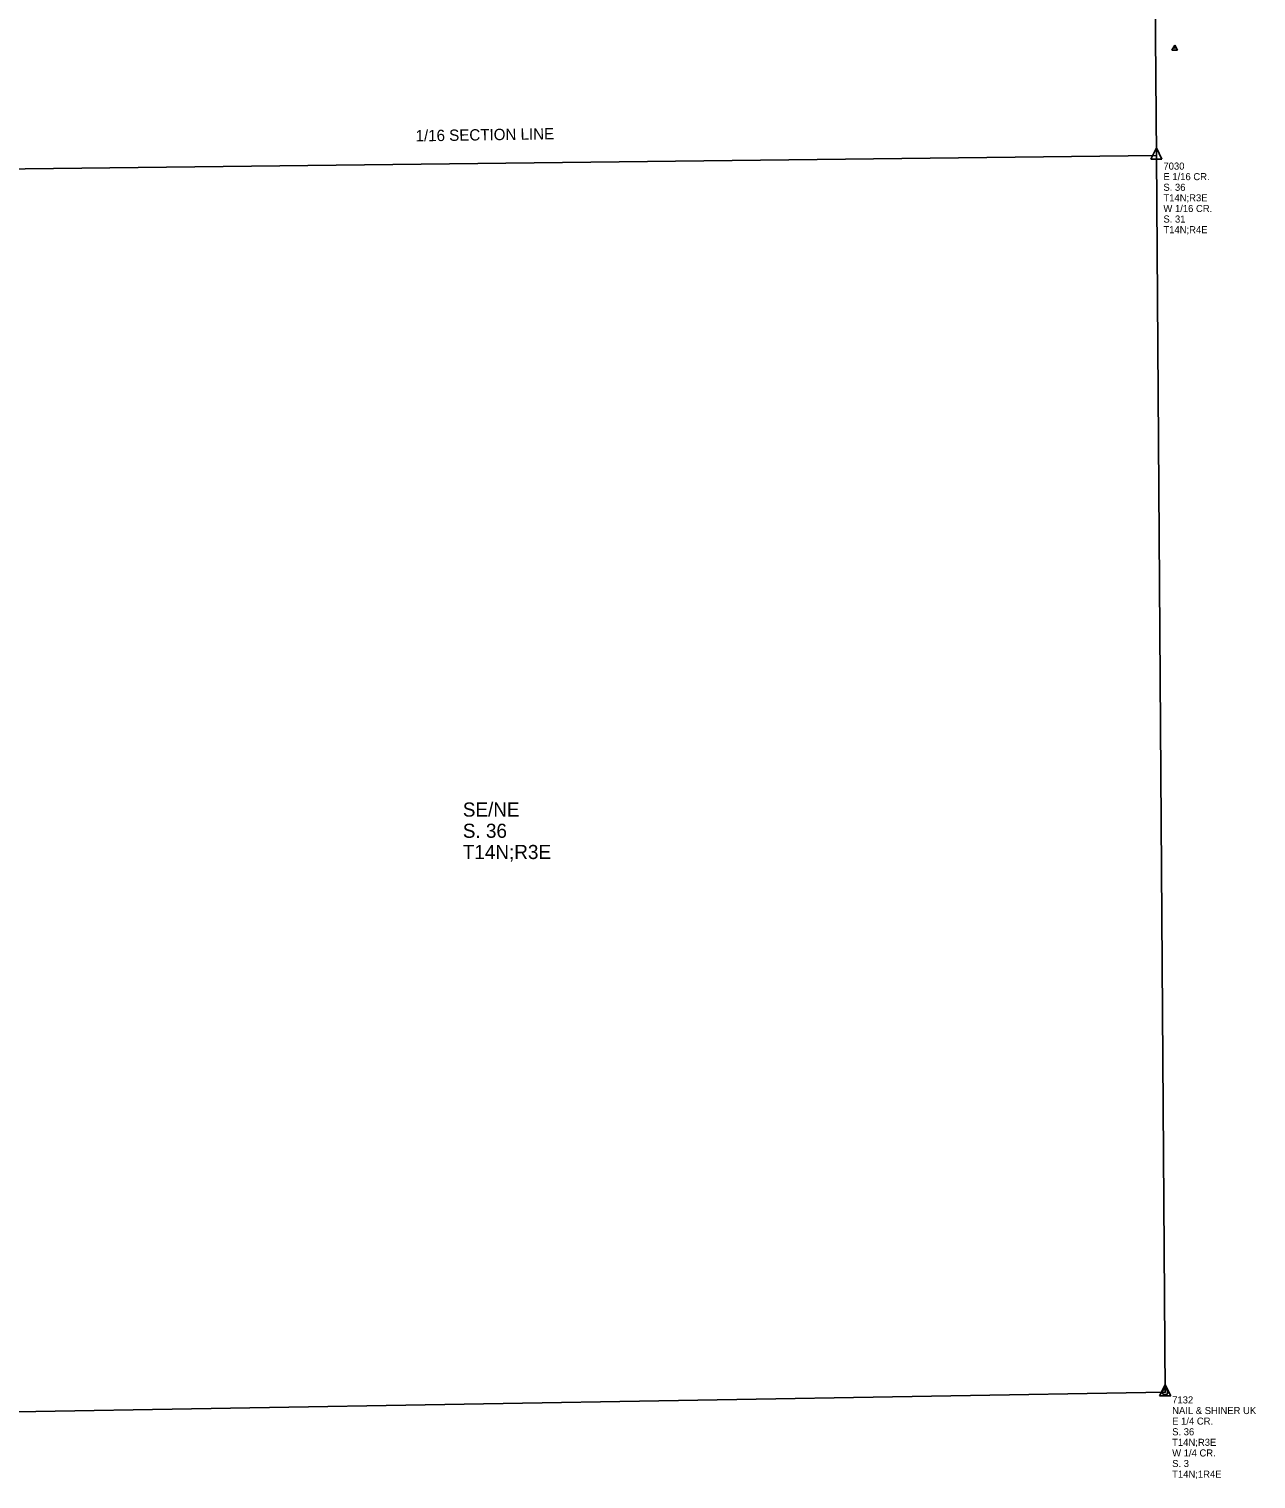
# Model space of a CAD drawing. Extents: x 1688544 to 1704497, y 535668 to 545444.
# Drawn here: x 1692576 to 1693878, y 536190 to 537729 of the extents above; entities that cross this region are included whole.
import ezdxf

# ---------------------------------------------------------------- set-up
doc = ezdxf.new("R2010")
doc.units = 0
for name, color, linetype in [('Default', 7, 'Continuous'), ('S_CAL_CORNER', 7, 'Continuous'), ('S_CAL_CORNER_ANNOT', 7, 'Continuous'), ('S_IRON_PIN', 7, 'Continuous'), ('S_IRON_PIN_ANNOT', 7, 'Continuous'), ('S_QSECTION', 7, 'Continuous'), ('S_SECONDARY_CTL', 7, 'Continuous'), ('S_SECTION', 7, 'Continuous'), ('S_SECTION_ANNOT', 7, 'Continuous'), ('S_SIXTEEN_SECTION', 7, 'Continuous')]:
    doc.layers.add(name, color=color, linetype=linetype)

msp = doc.modelspace()

# ---------------------------------------------------------------- linework, layer by layer
at = {"layer": 'S_CAL_CORNER'}
for p, q in [((1693772.7, 537602.7), (1693766.8, 537590.9)), ((1693772.7, 537602.7), (1693766.8, 537590.9)), ((1693772.7, 537602.7), (1693766.8, 537590.9)), ((1693766.8, 537590.9), (1693778.5, 537590.9)), ((1693766.8, 537590.9), (1693778.5, 537590.9)), ((1693766.8, 537590.9), (1693778.5, 537590.9)), ((1693772.7, 537602.7), (1693778.5, 537590.9)), ((1693772.7, 537602.7), (1693778.5, 537590.9)), ((1693772.7, 537602.7), (1693778.5, 537590.9)), ((1693781.9, 536290.3), (1693776.1, 536278.5)), ((1693781.9, 536290.3), (1693787.8, 536278.5)), ((1693776.1, 536278.5), (1693787.8, 536278.5))]:
    msp.add_line(p, q, dxfattribs=at)
at = {"layer": 'S_IRON_PIN'}
for radius in [2.91, 0.411, 0.212, 0.262, 0.145, 0.0581, 0.0822]:
    msp.add_circle((1693781.9, 536282.4), radius, dxfattribs=at)
at = {"layer": 'S_QSECTION'}
msp.add_line((1692471.9, 536259.9), (1693781.9, 536282.4), dxfattribs=at)
at = {"layer": 'S_SECONDARY_CTL'}
for p, q in [((1693792.1, 537711.6), (1693789.1, 537706.6)), ((1693789.1, 537706.6), (1693795.1, 537706.6)), ((1693792.1, 537711.6), (1693795.1, 537706.6))]:
    msp.add_line(p, q, dxfattribs=at)
for radius in [0.311, 0.183, 0.103]:
    msp.add_circle((1693792.1, 537709), radius, dxfattribs=at)
at = {"layer": 'S_SECTION'}
for p, q in [((1693763.3, 538907.1), (1693772.6, 537594.7)), ((1693772.6, 537594.7), (1693781.9, 536282.4))]:
    msp.add_line(p, q, dxfattribs=at)
at = {"layer": 'S_SIXTEEN_SECTION'}
msp.add_line((1692463.3, 537579.4), (1693772.6, 537594.7), dxfattribs=at)

# ---------------------------------------------------------------- texts
at = {"layer": 'Default'}
for s, p in [('SE/NE', (1693036.3, 536893.1)), ('S. 36', (1693036.3, 536870.6)), ('T14N;R3E', (1693036.3, 536848.1))]:
    msp.add_text(s, height=15, dxfattribs=at).set_placement(p)
at = {"layer": 'S_CAL_CORNER_ANNOT'}
for s, p in [('7030', (1693780.1, 537579.7)), ('E 1/16 CR.', (1693780.1, 537568.5)), ('S. 36 ', (1693780.1, 537557.2)), ('T14N;R3E', (1693780.1, 537546)), ('W 1/16 CR.', (1693780.1, 537534.7)), ('S. 31', (1693780.1, 537523.5)), ('T14N;R4E', (1693780.1, 537512.2))]:
    msp.add_text(s, height=7.5, dxfattribs=at).set_placement(p)
at = {"layer": 'S_IRON_PIN_ANNOT'}
for s, p in [('7132', (1693789.4, 536270.4)), ('NAIL & SHINER UK ', (1693789.4, 536259.1)), ('E 1/4 CR. ', (1693789.4, 536247.9)), ('S. 36', (1693789.4, 536236.6)), ('W 1/4 CR.', (1693789.4, 536214.1)), ('T14N;R3E', (1693789.4, 536225.4)), ('S. 3', (1693789.4, 536202.9)), ('T14N;1R4E', (1693789.4, 536191.6))]:
    msp.add_text(s, height=7.5, dxfattribs=at).set_placement(p)
at = {"layer": 'S_SECONDARY_CTL'}
msp.add_text('TV', height=1.5, dxfattribs=at).set_placement((1693790.9, 537707))
at = {"layer": 'S_SECTION_ANNOT'}
msp.add_text('1/16 SECTION LINE', height=12, rotation=0.8773, dxfattribs=at).set_placement((1692986.2, 537609.6))

doc.saveas('drawing.dxf')
